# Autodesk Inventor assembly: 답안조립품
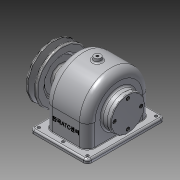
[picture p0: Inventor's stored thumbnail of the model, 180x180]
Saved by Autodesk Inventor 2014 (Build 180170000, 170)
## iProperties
Created: 2015-09
Part Number: 답안조립품
Document SubType Name: Assembly
Designer: Administrator
Author: Administrator
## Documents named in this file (13)
- C:\Users\Administrator\Desktop\450907V1045\답안조립품.iam
- C:\Users\Administrator\Desktop\450907V1045\1-본체.ipt
- C:\Users\Administrator\Desktop\450907V1045\뒤커버.ipt
- C:\Users\Administrator\Desktop\450907V1045\볼트 M3 x 8.ipt
- C:\Users\Administrator\Desktop\450907V1045\베어링 6203.ipt
- C:\Users\Administrator\Desktop\450907V1045\축.ipt
- C:\Users\Administrator\Desktop\450907V1045\스퍼기어.ipt
- C:\Users\Administrator\Desktop\450907V1045\키 - 6 x 6 x 22.ipt
- C:\Users\Administrator\Desktop\450907V1045\앞커버.ipt
- C:\Users\Administrator\Desktop\450907V1045\오일 실 17 32 8.ipt
- C:\Users\Administrator\Desktop\450907V1045\키 - 5 x 5 x 18.ipt
- C:\Users\Administrator\Desktop\450907V1045\V-벨트풀리.ipt
- C:\Users\Administrator\Desktop\450907V1045\멈춤나사 - M4x10.ipt
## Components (6 placed, 3 different names)
1. 1-본체:1
2. V-벨트풀리:1
3. ISO 4762 M3 x 8:1
4. ISO 4762 M3 x 8:2
5. ISO 4762 M3 x 8:3
6. ISO 4762 M3 x 8:4
